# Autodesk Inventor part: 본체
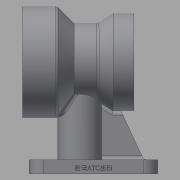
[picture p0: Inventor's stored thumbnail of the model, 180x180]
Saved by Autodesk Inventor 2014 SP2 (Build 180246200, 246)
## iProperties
Created: 2019-01
Part Number: 본체
Material: Generic
Document SubType Name: Modeling
Designer: CM-CAD
Density: 1 g/cm^3
Appearance: Default
Author: CM-CAD
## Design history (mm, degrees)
sketch "스케치1"
  geometry: C1 r 40 at (0, 0); 1 further point
  constraints: 1 centre point, 1 coincident
  dimensions: "d0" = 80 diameter of C1
extrude "돌출1" new body sketch "스케치1" distance "d1" = 80; taper "d2" = 0 deg
sketch "스케치2"
  geometry: L1 (0, 40)-(0, -40) reference; L2 (80, -40)-(80, 40) reference; L3 (0, 0)-(80, 0); L4 (0, 40)-(25, 40); L5 (25, 40)-(37.155, 28); L6 (37.155, 28)-(54.213, 28); L7 (54.213, 28)-(65, 35); L8 (65, 35)-(80, 35)
  constraints: 12 end point, 2 parallel, 2 point on line, 1 midpoint, 1 perpendicular
  dimensions: "d3" = 25 distance of L4.start L4.end; "d4" = 15 distance of L7.end L8.end; "d5" = 80 diameter of L4 L3; "d6" = 56 diameter of L6 L3; "d7" = 70 diameter of L8 L3
revolve "회전1" sketch "스케치2" stored, may be unused: angle "d8" = 90 deg
sketch "스케치3"
  geometry: L1 (0, 40)-(0, -40) reference; L2 (80, 35)-(80, -35) reference; L3 (0, 0)-(80, 0); L4 (0, 26)-(20, 26); L5 (20, 26)-(20, 16); L6 (20, 16)-(63, 16); L7 (63, 16)-(63, 20); L8 (63, 20)-(80, 20)
  constraints: 12 end point, 3 perpendicular, 2 parallel, 2 point on line, 1 midpoint
  dimensions: "d9" = 52 diameter of L4 L3; "d10" = 32 diameter of L6 L3; "d11" = 40 diameter of L8 L3; "d12" = 20 distance of L4.start L4.end; "d13" = 17 distance of L7.end L8.end
revolve "회전2" sketch "스케치3" stored, may be unused: angle "d14" = 90 deg
fillet "모깎기1" dims "d15" = 1
chamfer "모따기1" distance "d16" = 1; stored, may be unused: second distance "d17" = 2, angle "d18" = 45 deg
sketch "스케치4" dims "d19" = 66
  geometry: C1 r 27 at (0, 0) reference; 2 further points
  constraints: 1 coincident, 1 vertical alignment, 2 other
hole "구멍1" sketch "스케치4" at (0, 33) diameter "d20" = 3.242; stored, may be unused: countersink angle "d24" = 90 deg, drill point angle "d26" = 118 deg; dims "d21" = 9, "d22" = 4, "d23" = 2, "d25" = 11
sketch "스케치5" dims "d30" = 55
  geometry: C1 r 21 at (0, 0) reference; 2 further points
  constraints: 1 coincident, 1 vertical alignment, 2 other
hole "구멍2" sketch "스케치5" at (0, 27.5) diameter "d31" = 3.242; stored, may be unused: countersink angle "d35" = 90 deg, drill point angle "d37" = 118 deg; dims "d32" = 9, "d33" = 4, "d34" = 2, "d36" = 11
node "작업 평면1"
sketch "스케치6"
  geometry: L1 (40, 25)-(-40, 25) reference; L2 (-40, 57)-(40, 57); L3 (-40, 25)-(40, 25); L4 (-44.948, 41)-(42.771, 41); C1 r 16 at (0, 41); 2 further points
  constraints: 6 end point, 2 parallel, 1 centre point, 1 collinear, 1 midpoint, 1 point on line
  dimensions: "d42" = 32 distance between parallel lines of L2 L1; "d43" = 16 distance between parallel lines of L2 L4; "d44" = 32 diameter of C1
extrude "돌출2" join sketch "스케치6" distance "d45" = 20; taper "d46" = 0 deg
sketch "스케치7"
  geometry: 3 further points
  constraints: 1 vertical alignment
extrude "돌출3" join sketch "스케치7" distance "d47" = 40; taper "d48" = 0 deg
sketch "스케치8"
  geometry: L1 (0, 0)-(-46, 0); L2 (-46, -36)-(48.584, -36); L3 (-46, -36)-(-46, 56); L4 (46, -36)-(46, 56); L5 (-46, 56)-(46, 56); C1 r 16 at (0, 0) reference; 1 further point
  constraints: 10 end point, 2 parallel, 2 perpendicular, 2 point on line, 1 horizontal
  dimensions: "d49" = 36 distance between parallel lines of L2 L1; "d50" = 46 distance from line of L3 L1.start; "d51" = 92 distance between parallel lines of L4 L3; "d52" = 92 distance between parallel lines of L5 L2
extrude "돌출4" join sketch "스케치8" distance "d53" = 10; taper "d54" = 0 deg
sketch "스케치9"
  geometry: L1 (97, 70)-(5, 70) reference; L2 (80, 35)-(65, 35) reference; L3 (65, 35)-(57, 29.809) reference; L4 (57, 70)-(57, 29.809) reference; L5 (57, 5.665)-(87, 70); L6 (97, 80)-(97, 70) reference; 2 further points
  constraints: 4 point on line, 2 end point
  dimensions: "d55" = 25 deg angle of L6 L5; "d56" = 10 distance of L1.start L5.end
extrude "돌출5" join sketch "스케치9" stored distance "d57" = 10; taper "d58" = 0 deg
fillet "모깎기2" dims "d59" = 10
sketch "스케치10"
  geometry: A1 r 10 centre (-36, -26) between (-46, -26) and (-36, -36) reference; A2 r 10 centre (36, -26) between (36, -36) and (46, -26) reference; A3 r 10 centre (36, 46) between (46, 46) and (36, 56) reference; A4 r 10 centre (-36, 46) between (-36, 56) and (-46, 46) reference; 5 further points
  constraints: 4 coincident
hole "구멍3" sketch "스케치10" at (-36, 46), (36, 46), (36, -26), (-36, -26) diameter "d60" = 9; stored, may be unused: countersink angle "d64" = 90 deg, drill point angle "d66" = 118 deg; dims "d61" = 9, "d62" = 4, "d63" = 2, "d65" = 10
fillet "모깎기3" dims "d67" = 3
fillet "모깎기4" dims "d68" = 3
fillet "모깎기5" dims "d69" = 3
fillet "모깎기6" dims "d70" = 3
fillet "모깎기7" dims "d71" = 3
fillet "모깎기8" dims "d72" = 3
fillet "모깎기9" dims "d73" = 3
fillet "모깎기10" dims "d74" = 3
fillet "모깎기11" dims "d75" = 3
fillet "모깎기12" dims "d76" = 3
fillet "모깎기13" dims "d77" = 3
fillet "모깎기14" dims "d78" = 3
fillet "모깎기15" dims "d79" = 3
fillet "모깎기16" dims "d80" = 3
fillet "모깎기17" dims "d81" = 3
fillet "모깎기18" dims "d82" = 3
sketch "스케치11"
  geometry: L1 (0, 0)-(0, 72) reference; L2 (-10, -10)-(0, -10) reference; 2 further points
  constraints: 1 other
  dimensions: "d83" = 46 distance from line of point (-4, 36) L2; "d84" = 4 distance from line of L1 point (-4, 36)
feature "엠보싱1" sketch "스케치11" dims "d0" = 80, "d9" = 52, "d10" = 32, "d11" = 40, "d12" = 20, "d13" = 17, "d85" = 0.5, "d86" = 0
node "솔리드1"
pattern_circular "원형 패턴1" dims angle "d28" = 360 deg
pattern_circular "원형 패턴2" dims angle "d39" = 360 deg
